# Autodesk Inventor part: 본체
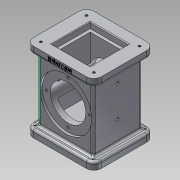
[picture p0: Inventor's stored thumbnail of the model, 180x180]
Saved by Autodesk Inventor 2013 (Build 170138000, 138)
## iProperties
Created: 2017-08
Part Number: 본체
Material: 알루미늄 6061
Document SubType Name: Modeling
Designer: Administrator
Density: 1 g/cm^3
Author: Administrator
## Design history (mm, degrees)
sketch "스케치1"
  geometry: L1 (-46, -41)-(46, -41); L2 (46, -41)-(46, 41); L3 (46, 41)-(-46, 41); L4 (-46, 41)-(-46, -41); L5 (-46, -41)-(46, 41); L6 (46, -41)-(-46, 41); 1 further point
  constraints: 12 end point, 2 midpoint, 2 parallel, 1 horizontal, 1 perpendicular
  dimensions: "d0" = 92 distance of L3.end L2.end; "d1" = 82 distance of L2.end L1.end
extrude "돌출1" new body sketch "스케치1" distance "d2" = 10; taper "d3" = 0 deg
sketch "스케치2"
  geometry: L1 (-37, -33)-(37, -33); L2 (37, -33)-(37, 33); L3 (37, 33)-(-37, 33); L4 (-37, 33)-(-37, -33); L5 (-37, -33)-(37, 33); L6 (37, -33)-(-37, 33); 1 further point
  constraints: 12 end point, 2 midpoint, 2 parallel, 1 horizontal, 1 perpendicular
  dimensions: "d4" = 74 distance of L3.end L2.end; "d5" = 66 distance of L2.end L1.end
extrude "돌출2" join sketch "스케치2" distance "d6" = 88; taper "d7" = 0 deg
sketch "스케치3"
  geometry: L1 (-46, -41)-(46, -41); L2 (46, -41)-(46, 41); L3 (46, 41)-(-46, 41); L4 (-46, 41)-(-46, -41); L5 (-46, -41)-(46, 41); L6 (46, -41)-(-46, 41); 1 further point
  constraints: 12 end point, 2 midpoint, 2 parallel, 1 horizontal, 1 perpendicular
  dimensions: "d8" = 92 distance of L3.end L2.end; "d9" = 82 distance of L2.end L1.end
extrude "돌출3" join sketch "스케치3" distance "d10" = 10; taper "d11" = 0 deg
sketch "스케치4"
  geometry: L1 (-24, -24)-(24, -24); L2 (24, -24)-(24, 24); L3 (24, 24)-(-24, 24); L4 (-24, 24)-(-24, -24); L5 (-24, -24)-(24, 24); L6 (24, -24)-(-24, 24); 1 further point
  constraints: 12 end point, 2 midpoint, 2 parallel, 1 horizontal, 1 perpendicular
  dimensions: "d12" = 48 distance of L3.end L2.end; "d13" = 48 distance of L2.end L1.end
extrude "돌출4" cut sketch "스케치4" distance "d14" = 16; taper "d15" = 0 deg
sketch "스케치5"
  geometry: L1 (74, 0)-(0, 0) reference; L2 (74, 0)-(74, 88) reference; L3 (0, 88)-(74, 88) reference; L4 (0, 0)-(0, 88) reference; 1 further point
sketch "스케치6"
  geometry: L1 (-33, 10)-(33, 10) reference; L2 (-33, 10)-(-33, 98) reference; L3 (33, 98)-(-33, 98) reference; L4 (33, 10)-(33, 98) reference; L5 (-33, 89)-(-30, 89); L6 (-30, 89)-(-30, 78); L7 (-30, 78)-(30, 78); L8 (30, 78)-(30, 89); L9 (30, 89)-(33, 89); L10 (-33, 54)-(33, 54); L11 (41, 0)-(-41, 0) reference; L12 (-33, 89)-(-33, 54); L13 (33, 54)-(33, 89); L14 (33, 54)-(-33, 54); 1 further point
  constraints: 18 end point, 3 collinear, 3 perpendicular, 2 midpoint, 2 parallel, 2 point on line, 1 horizontal, 1 horizontal alignment
  dimensions: "d16" = 3 distance of L5.start L5.end; "d18" = 3 distance of L8.end L9.end; "d19" = 54 distance between parallel lines of L11 L10; "d20" = 70 diameter of L5 L10; "d21" = 48 diameter of L7 L10
revolve "회전1" sketch "스케치6" stored, may be unused: angle "d22" = 90 deg
sketch "스케치7"
  geometry: L1 (-26, -26)-(26, -26); L2 (26, -26)-(26, 26); L3 (26, 26)-(-26, 26); L4 (-26, 26)-(-26, -26); L5 (-26, -26)-(26, 26); L6 (26, -26)-(-26, 26); 1 further point
  constraints: 12 end point, 2 midpoint, 2 parallel, 1 horizontal, 1 perpendicular
  dimensions: "d23" = 52 distance of L3.end L2.end; "d24" = 52 distance of L1.end L2.end
extrude "돌출5" cut sketch "스케치7" distance "d25" = 8; taper "d26" = 0 deg
sketch "스케치8"
  geometry: L1 (-22, -22)-(22, -22); L2 (22, -22)-(22, 22); L3 (22, 22)-(-22, 22); L4 (-22, 22)-(-22, -22); L5 (-22, -22)-(22, 22); L6 (22, -22)-(-22, 22); 1 further point
  constraints: 12 end point, 2 midpoint, 2 parallel, 1 horizontal, 1 perpendicular
  dimensions: "d27" = 44 distance of L3.end L2.end; "d28" = 44 distance of L2.end L1.end
extrude "돌출6" cut sketch "스케치8" distance "d29" = 74; taper "d30" = 0 deg
sketch "스케치9"
  geometry: L1 (-36, -31)-(36, -31); L2 (36, -31)-(36, 31); L3 (36, 31)-(-36, 31); L4 (-36, 31)-(-36, -31); L5 (-36, -31)-(36, 31); L6 (36, -31)-(-36, 31); 5 further points
  constraints: 12 end point, 4 coincident, 2 midpoint, 2 parallel, 1 horizontal, 1 perpendicular
  dimensions: "d31" = 72 distance of L3.end L2.end; "d32" = 62 distance of L2.end L1.end
hole "구멍1" sketch "스케치9" at (-36, 31), (36, 31), (36, -31), (-36, -31) diameter "d33" = 3.242; stored, may be unused: countersink angle "d37" = 90 deg, drill point angle "d39" = 118 deg; dims "d34" = 4, "d35" = 4, "d36" = 2, "d38" = 6
sketch "스케치10"
  geometry: L1 (-36, -31)-(36, -31); L2 (36, -31)-(36, 31); L3 (36, 31)-(-36, 31); L4 (-36, 31)-(-36, -31); L5 (-36, -31)-(36, 31); L6 (36, -31)-(-36, 31); 5 further points
  constraints: 12 end point, 4 coincident, 2 midpoint, 2 parallel, 1 horizontal, 1 perpendicular
  dimensions: "d40" = 72 distance of L3.end L2.end; "d41" = 62 distance of L2.end L1.end
hole "구멍2" sketch "스케치10" at (-36, 31), (36, 31), (36, -31), (-36, -31) diameter "d42" = 3.242; stored, may be unused: countersink angle "d46" = 90 deg, drill point angle "d48" = 118 deg; dims "d43" = 4, "d44" = 4, "d45" = 2, "d47" = 6
fillet "모깎기1" dims "d49" = 10
fillet "모깎기2" dims "d50" = 3
fillet "모깎기3" dims "d51" = 3
sketch "스케치11"
  geometry: L1 (0, 0)-(72, 0) reference; L2 (-10, 0)-(-10, -7) reference; 2 further points
  constraints: 1 other
  dimensions: "d52" = 46 distance from line of L2 point (36, -4); "d53" = 4 distance from line of L1 point (36, -4)
feature "엠보싱1" sketch "스케치11" dims "d0" = 92, "d1" = 82, "d8" = 92, "d9" = 82, "d54" = 0.5, "d55" = 0
fillet "모깎기4" dims "d56" = 3
chamfer "모따기1" distance "d57" = 1; stored, may be unused: second distance "d58" = 2, angle "d59" = 45 deg
sketch "스케치12" dims "d60" = 58
  geometry: C1 r 35 at (0, 0) reference; 3 further points
  constraints: 2 vertical alignment, 1 coincident, 2 other
hole "구멍3" sketch "스케치12" at (0, 29) diameter "d61" = 3.242; stored, may be unused: countersink angle "d65" = 90 deg, drill point angle "d67" = 118 deg; dims "d62" = 4, "d63" = 4, "d64" = 2, "d66" = 6
sketch "스케치13"
  geometry: L1 (13, -1)-(13, 61) reference; 4 further points
  constraints: 2 horizontal alignment, 1 midpoint
  dimensions: "d71" = 38 distance from line of L1 point (-25, 30); "d72" = 42 distance of point (-25, 30) point (-67, 30)
hole "구멍4" sketch "스케치13" at (-67, 30), (-25, 30) diameter "d73" = 4.134; stored, may be unused: countersink angle "d77" = 90 deg, drill point angle "d79" = 0 deg; dims "d74" = 30, "d75" = 4, "d76" = 2, "d78" = 30
node "솔리드1"
pattern_circular "원형 패턴1" dims angle "d69" = 360 deg
mirror "대칭1"
node "투영된 루프1"
